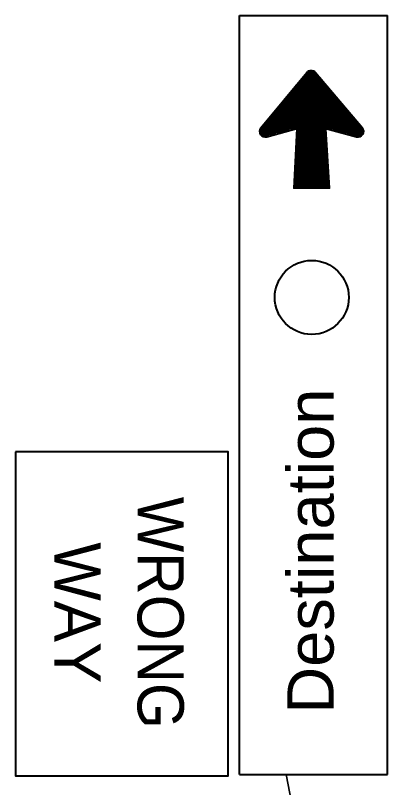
# Model space of a CAD drawing. Extents: x -198 to 658, y -402 to 142.
# Drawn here: x 205.87 to 229.06, y 2.79 to 50.83 of the extents above; entities that cross this region are included whole.
import ezdxf
from ezdxf.enums import TextEntityAlignment as Align

# ---------------------------------------------------------------- set-up
doc = ezdxf.new("R2010")
doc.units = 0
doc.header["$LTSCALE"] = 0.96
doc.layers.add('1', color=7, linetype='Continuous', lineweight=35)

msp = doc.modelspace()

# ---------------------------------------------------------------- linework, layer by layer
at = {"layer": '1', "lineweight": 40}
for p, q in [((219.8401, 3.5957), (219.8401, 50.8277)), ((219.8401, 50.8277), (229.0561, 50.8277)), ((229.0561, 3.5957), (229.0561, 50.8277)), ((224.7188, 47.1086), (223.8779, 47.1086)), ((224.3502, 47.1086), (223.8779, 47.1086)), ((224.6267, 47.2238), (223.97, 47.2238)), ((224.3502, 47.2238), (223.97, 47.2238)), ((225.1105, 46.6478), (223.4977, 46.6478)), ((224.3502, 46.6478), (223.4977, 46.6478)), ((225.0183, 46.763), (223.5899, 46.763)), ((224.3502, 46.763), (223.5899, 46.763)), ((224.9147, 46.8782), (223.6935, 46.8782)), ((224.3502, 46.8782), (223.6935, 46.8782)), ((224.8225, 46.9934), (223.7857, 46.9934)), ((224.3502, 46.9934), (223.7857, 46.9934)), ((225.4907, 46.187), (223.1175, 46.187)), ((224.3502, 46.187), (223.1175, 46.187)), ((225.387, 46.3022), (223.2097, 46.3022)), ((224.3502, 46.3022), (223.2097, 46.3022)), ((225.2948, 46.4174), (223.3019, 46.4174)), ((224.3502, 46.4174), (223.3019, 46.4174)), ((225.2027, 46.5326), (223.4055, 46.5326)), ((224.3502, 46.5326), (223.4055, 46.5326)), ((225.8823, 45.7262), (222.7374, 45.7262)), ((224.3502, 45.7262), (222.7374, 45.7262)), ((225.7787, 45.8414), (222.8295, 45.8414)), ((224.3502, 45.8414), (222.8295, 45.8414)), ((225.6865, 45.9566), (222.9217, 45.9566)), ((224.3502, 45.9566), (222.9217, 45.9566)), ((225.5828, 46.0718), (223.0254, 46.0718)), ((224.3502, 46.0718), (223.0254, 46.0718)), ((226.274, 45.2654), (222.3572, 45.2654)), ((224.3502, 45.2654), (222.3572, 45.2654)), ((226.1703, 45.3806), (222.4494, 45.3806)), ((224.3502, 45.3806), (222.4494, 45.3806)), ((226.0782, 45.4958), (222.5415, 45.4958)), ((224.3502, 45.4958), (222.5415, 45.4958)), ((225.9745, 45.611), (222.6452, 45.611)), ((224.3502, 45.611), (222.6452, 45.611)), ((226.7579, 44.6895), (221.8734, 44.6895)), ((224.3502, 44.6895), (221.8734, 44.6895)), ((226.6542, 44.8046), (221.9771, 44.8046)), ((224.3502, 44.8046), (221.9771, 44.8046)), ((226.562, 44.9198), (222.0692, 44.9198)), ((224.3502, 44.9198), (222.0692, 44.9198)), ((226.4699, 45.035), (222.1614, 45.035)), ((224.3502, 45.035), (222.1614, 45.035)), ((226.3662, 45.1502), (222.2651, 45.1502)), ((224.3502, 45.1502), (222.2651, 45.1502)), ((227.1495, 44.2287), (221.4932, 44.2287)), ((224.3502, 44.2287), (221.4932, 44.2287)), ((227.0459, 44.3439), (221.5969, 44.3439)), ((224.3502, 44.3439), (221.5969, 44.3439)), ((226.9537, 44.4591), (221.6891, 44.4591)), ((224.3502, 44.4591), (221.6891, 44.4591)), ((226.85, 44.5743), (221.7812, 44.5743)), ((224.3502, 44.5743), (221.7812, 44.5743)), ((227.4375, 43.8831), (221.2167, 43.8831)), ((224.3502, 43.8831), (221.2167, 43.8831)), ((227.3454, 43.9983), (221.3089, 43.9983)), ((224.3502, 43.9983), (221.3089, 43.9983)), ((227.2417, 44.1135), (221.4011, 44.1135)), ((224.3502, 44.1135), (221.4011, 44.1135)), ((224.3502, 43.7679), (223.4055, 43.7679)), ((222.9563, 43.6527), (221.09, 43.6527)), ((222.9563, 43.6527), (221.09, 43.6527)), ((222.53, 43.5375), (221.09, 43.5375)), ((222.53, 43.5375), (221.09, 43.5375)), ((225.2487, 43.3071), (223.3825, 43.3071)), ((224.3502, 43.3071), (223.3825, 43.3071)), ((225.2372, 43.5375), (223.394, 43.5375)), ((224.3502, 43.5375), (223.394, 43.5375)), ((225.2372, 43.4223), (223.394, 43.4223)), ((224.3502, 43.4223), (223.394, 43.4223)), ((225.2257, 43.6527), (223.4055, 43.6527)), ((224.3502, 43.6527), (223.4055, 43.6527)), ((227.5643, 43.6527), (225.6404, 43.6527)), ((227.5182, 43.4223), (226.5044, 43.4223)), ((225.2718, 42.8463), (223.3595, 42.8463)), ((224.3502, 42.8463), (223.3595, 42.8463)), ((225.2603, 43.0767), (223.371, 43.0767)), ((224.3502, 43.0767), (223.371, 43.0767)), ((225.2718, 42.9615), (223.371, 42.9615)), ((224.3502, 42.9615), (223.371, 42.9615)), ((225.2603, 43.1919), (223.3825, 43.1919)), ((224.3502, 43.1919), (223.3825, 43.1919)), ((225.2948, 42.3855), (223.3364, 42.3855)), ((224.3502, 42.3855), (223.3364, 42.3855)), ((225.2948, 42.6159), (223.3479, 42.6159)), ((224.3502, 42.6159), (223.3479, 42.6159)), ((225.2948, 42.5007), (223.3479, 42.5007)), ((224.3502, 42.5007), (223.3479, 42.5007)), ((225.2833, 42.7311), (223.3595, 42.7311)), ((224.3502, 42.7311), (223.3595, 42.7311)), ((225.3294, 41.8095), (223.3019, 41.8095)), ((224.3502, 41.8095), (223.3019, 41.8095)), ((225.3294, 41.9247), (223.3134, 41.9247)), ((224.3502, 41.9247), (223.3134, 41.9247)), ((225.3063, 42.1551), (223.3249, 42.1551)), ((224.3502, 42.1551), (223.3249, 42.1551)), ((225.3179, 42.0399), (223.3249, 42.0399)), ((224.3502, 42.0399), (223.3249, 42.0399)), ((225.3063, 42.2703), (223.3364, 42.2703)), ((224.3502, 42.2703), (223.3364, 42.2703)), ((225.3639, 41.3487), (223.2788, 41.3487)), ((224.3502, 41.3487), (223.2788, 41.3487)), ((225.3409, 41.5791), (223.2903, 41.5791)), ((224.3502, 41.5791), (223.2903, 41.5791)), ((225.3524, 41.4639), (223.2903, 41.4639)), ((224.3502, 41.4639), (223.2903, 41.4639)), ((225.3409, 41.6943), (223.3019, 41.6943)), ((224.3502, 41.6943), (223.3019, 41.6943)), ((225.387, 40.8879), (223.2558, 40.8879)), ((224.3502, 40.8879), (223.2558, 40.8879)), ((225.3755, 41.1183), (223.2673, 41.1183)), ((224.3502, 41.1183), (223.2673, 41.1183)), ((225.387, 41.0031), (223.2673, 41.0031)), ((224.3502, 41.0031), (223.2673, 41.0031)), ((225.3639, 41.2335), (223.2788, 41.2335)), ((224.3502, 41.2335), (223.2788, 41.2335)), ((225.4215, 40.4271), (223.2327, 40.4271)), ((224.3502, 40.4271), (223.2327, 40.4271)), ((225.3985, 40.6575), (223.2443, 40.6575)), ((224.3502, 40.6575), (223.2443, 40.6575)), ((225.41, 40.5423), (223.2443, 40.5423)), ((224.3502, 40.5423), (223.2443, 40.5423)), ((225.3985, 40.7727), (223.2558, 40.7727)), ((224.3502, 40.7727), (223.2558, 40.7727)), ((225.4446, 40.0815), (223.2097, 40.0815)), ((224.3502, 40.0815), (223.2097, 40.0815)), ((225.4331, 40.1967), (223.2212, 40.1967)), ((224.3502, 40.1967), (223.2212, 40.1967)), ((225.4215, 40.3119), (223.2327, 40.3119)), ((224.3502, 40.3119), (223.2327, 40.3119)), ((219.8401, 3.5957), (229.0561, 3.5957))]:
    msp.add_line(p, q, dxfattribs=at)
at = {"layer": '1'}
for p, q in [((221.1591, 43.8255), (224.0161, 47.2814)), ((224.5691, 47.2814), (227.4836, 43.837))]:
    msp.add_line(p, q, dxfattribs=at)
at = {"layer": '1', "lineweight": 40}
for points in [[(224.3502, 47.339), (224.0967, 47.339), (224.0852, 47.339)], [(224.4999, 47.339), (224.523, 47.339), (224.4999, 47.339), (224.0967, 47.339), (224.0967, 47.339)], [(223.371, 43.7679), (221.1361, 43.7679), (221.1246, 43.7679)], [(223.371, 43.7679), (221.1361, 43.7679), (221.1246, 43.7679)], [(227.5297, 43.7679), (227.5182, 43.7679), (225.2142, 43.7679), (223.4055, 43.7679)], [(222.1153, 43.4223), (221.1361, 43.4223), (221.1246, 43.4223)], [(222.1153, 43.4223), (221.1361, 43.4223), (221.1246, 43.4223)], [(221.7006, 43.3071), (221.2398, 43.3071), (221.2283, 43.3071)], [(221.7006, 43.3071), (221.2398, 43.3071), (221.2283, 43.3071)], [(227.5643, 43.5375), (227.5527, 43.5375), (226.0782, 43.5375)], [(227.4145, 43.3071), (227.403, 43.3071), (226.9307, 43.3071)]]:
    msp.add_lwpolyline(points, dxfattribs=at)
at = {"layer": '1'}
for points in [[(227.115, 43.261), (225.2142, 43.7679), (225.4446, 40.0815), (223.2097, 40.0815), (223.4055, 43.7794), (221.5278, 43.261)], [(221.5604, -16.1878), (226.5648, -16.1878), (222.7482, 3.5957)]]:
    msp.add_lwpolyline(points, dxfattribs=at)
at = {"layer": '1', "lineweight": 40}
msp.add_lwpolyline([(205.8721, 23.6837), (205.8721, 3.5237), (219.1201, 3.5237), (219.1201, 23.6837)], close=True, dxfattribs=at)
msp.add_circle((224.3336, 33.2851), 2.304, dxfattribs=at)
at = {"layer": '1'}
for centre, start, end in [((224.2923, 47.0532), 40.25653, 140.40471), ((221.4363, 43.602), 140.43005, 285.55122), ((227.2123, 43.6062), 255.11373, 40.25762)]:
    msp.add_arc(centre, 0.3571, start, end, dxfattribs=at)

# ---------------------------------------------------------------- texts
for s, rotation, width, p in [('Destination', 90, 1.05, (225.6961, 17.497)), ('WRONG', 270, 0.95, (213.4801, 13.6684))]:
    msp.add_text(s, height=2.88, rotation=rotation, dxfattribs=dict(at, width=width)).set_placement(p, align=Align.CENTER)
msp.add_text('WAY', height=2.88, rotation=270, dxfattribs=at).set_placement((208.2961, 13.6618), align=Align.CENTER)

doc.saveas('drawing.dxf')
